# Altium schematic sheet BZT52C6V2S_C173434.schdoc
size 127 x 101 mm
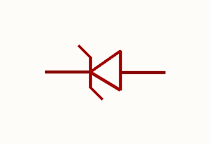
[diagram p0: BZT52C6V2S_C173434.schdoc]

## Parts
D?  bzt52c6v2s_c173434  [SOD-323_L1.8-W1.3-LS2.5-RD]  (value not drawn)

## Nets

Not connected (* = marked no-connect by the designer): D? 1 2

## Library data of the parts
D? = bzt52c6v2s_c173434: 二极管配置:1个独立式;稳压值(标称值):6.2V;稳压值(范围值):5.8V~6.6V;耗散功率(Pd):200mW;; Manufacturer: MDD(辰达半导体); AddInBom: yes; ModelId: db63db13d9e342eb939127d413d6200b; ModelTransform: 104.3305,51.181,0,0,0,0,0,-0.004,0; Diode Configuration: 1个独立式; Zener Voltage(Nom): 6.2V; Reverse Leakage Current (Ir): 1uA@3V; Pd - Power Dissipation: 200mW; Impedance(Zzt): 50Ω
